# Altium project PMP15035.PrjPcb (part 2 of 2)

## Sheet LM5170ControllerStage1.SchDoc
size 431 x 279 mm; Date: Not shown in title block; ApprovedBy: Not shown in title block; CheckedBy: Not shown in title block; Author: Not shown in title block; CompanyName: Not shown in title block; Engineer: Not shown in title block; Organization: Not shown in title block; Address1: Not shown in title block; Address2: Not shown in title block; Address3: Not shown in title block; Address4: Not shown in title block; DocumentNumber: 4; Revision: Use project parameter SCH_Rev; SheetNumber: 4; SheetTotal: 9; PageSetup: Record=PageOptions¦CenterHorizontal=True¦CenterVertical=True¦PrintScale=1.00¦XCorrection=1.00¦YCorrection=1.00¦PrintKind=0¦BorderSize=5000000¦LeftOffset=0¦BottomOffset=0¦Orientation=2¦PaperLength=1000¦PaperWidth=1000¦Scale=100¦PaperSource=15¦PrintQuality=600¦MediaType=1¦DitherType=10¦PaperKind=Letter¦PrintScaleMode=1
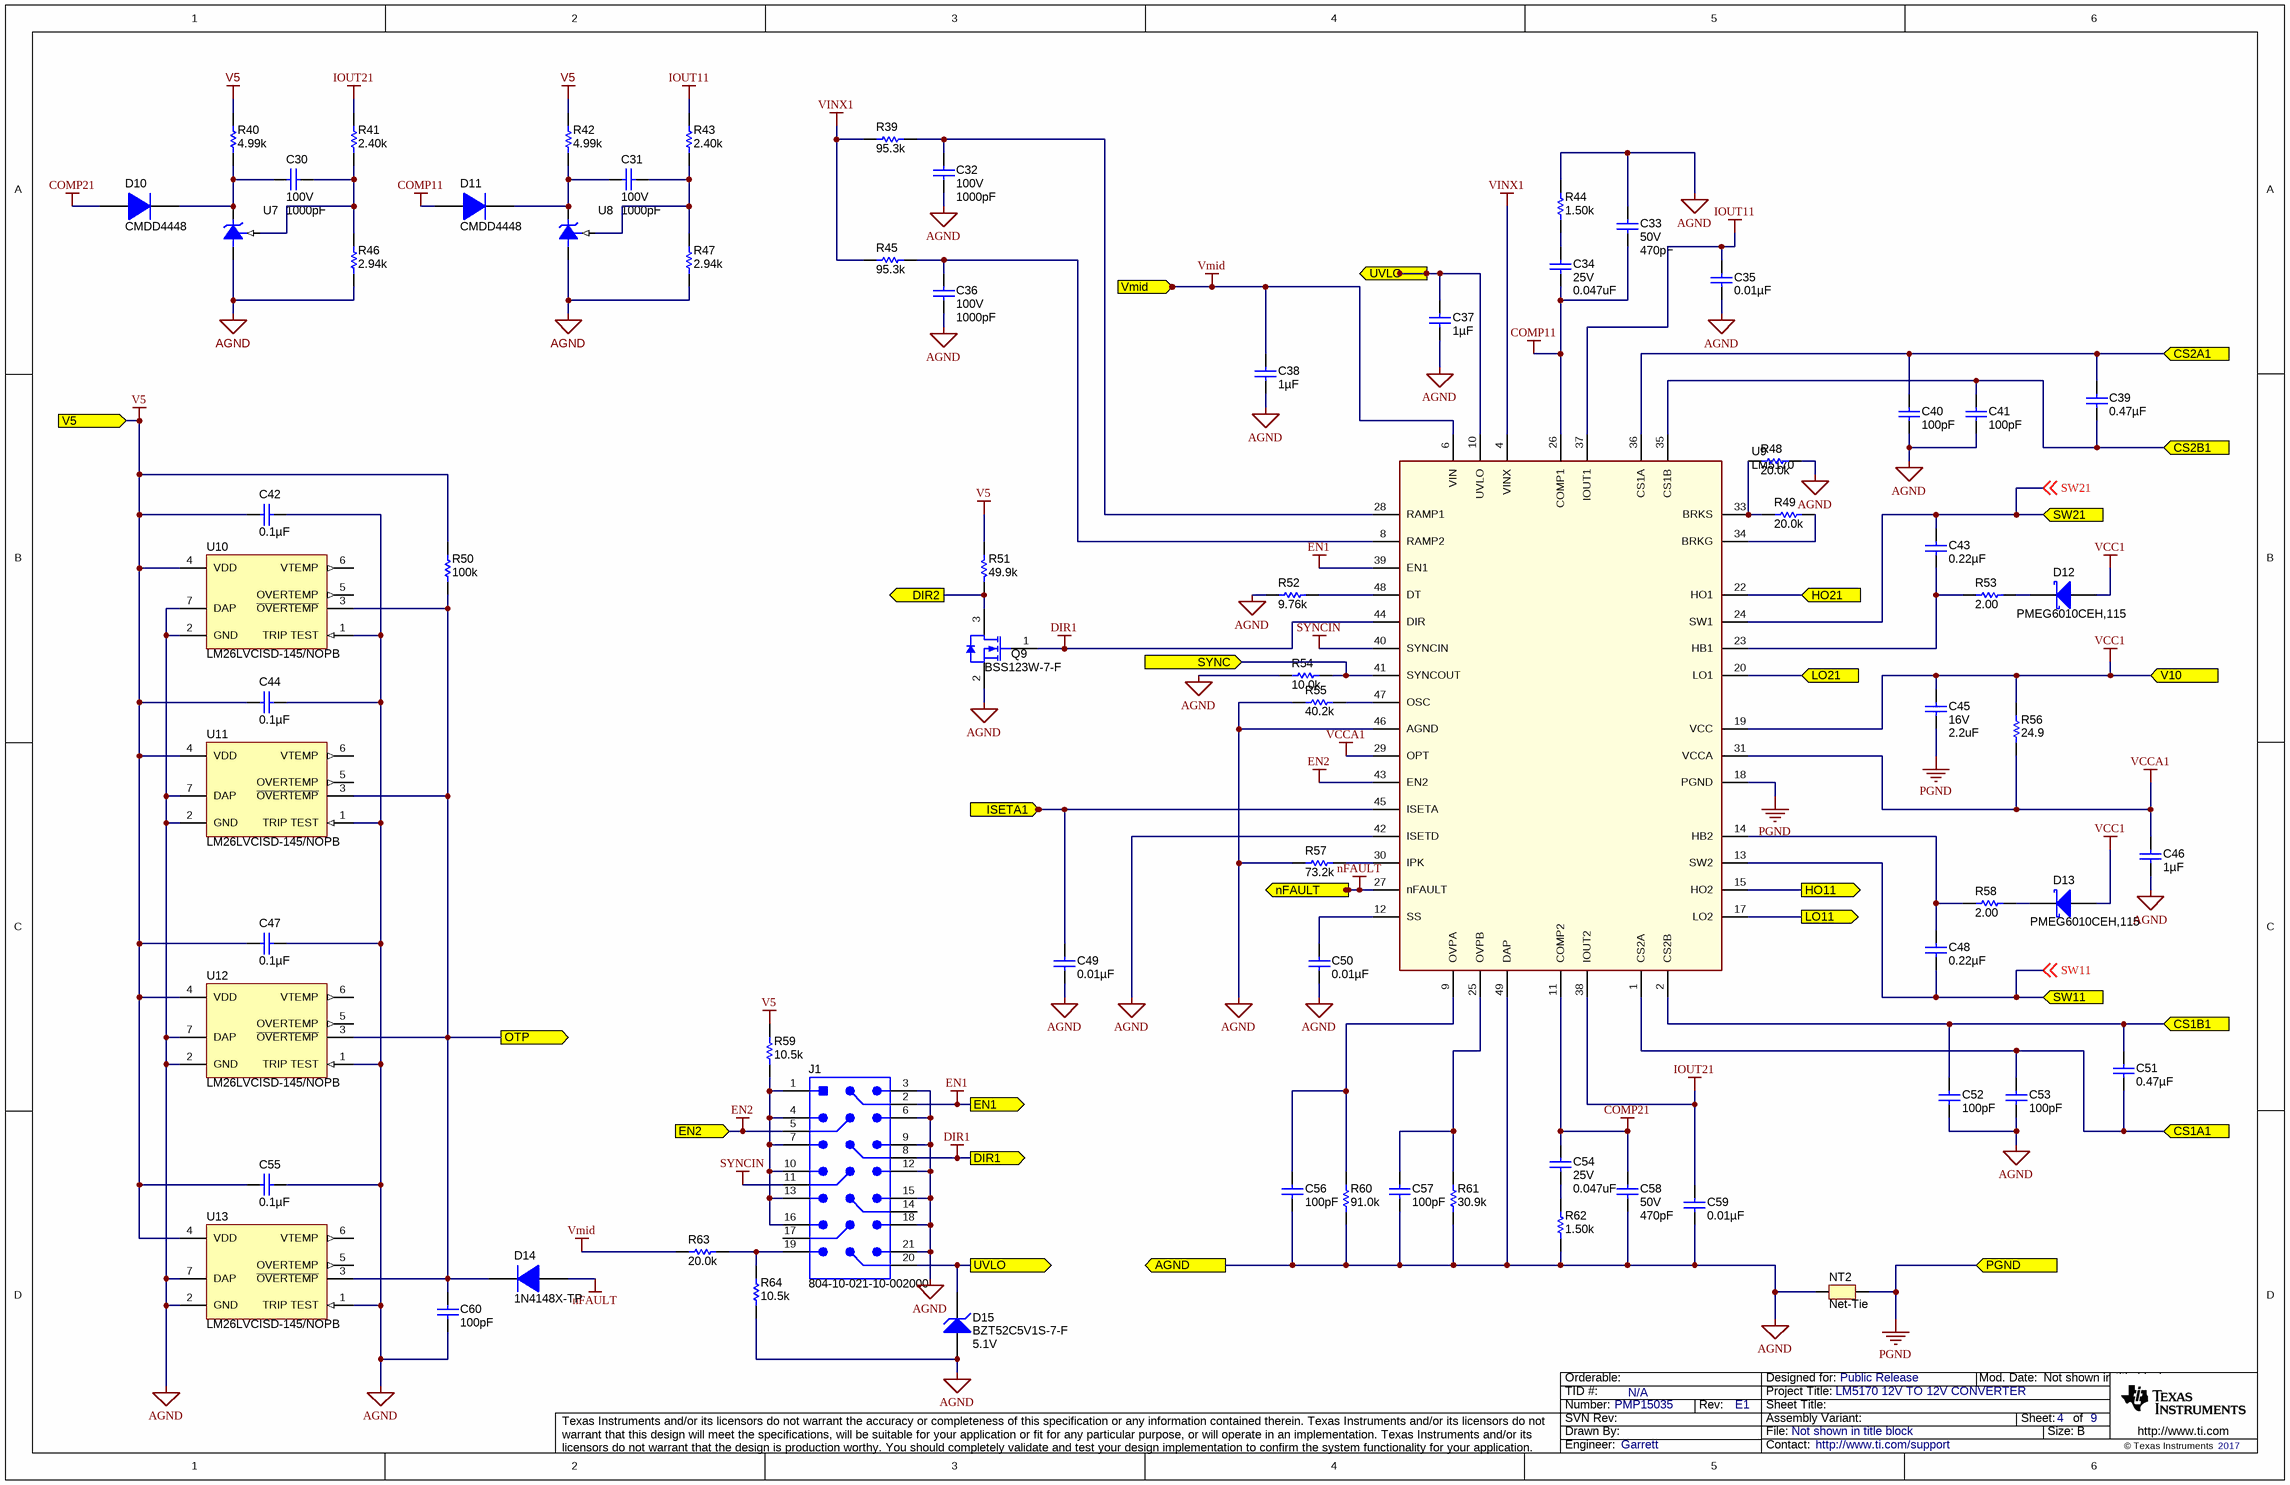
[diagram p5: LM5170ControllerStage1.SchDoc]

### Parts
C30  VDC_V: 100V  ValueDisplayed: 1000pF  [0603L]  (hidden comment: C1608C0G2A102J080AA)
C31  VDC_V: 100V  ValueDisplayed: 1000pF  [0603L]  (hidden comment: C1608C0G2A102J080AA)
C32  VDC_V: 100V  ValueDisplayed: 1000pF  [0603L]  (hidden comment: C1608C0G2A102J080AA)
C33  VDC_V: 50V  ValueDisplayed: 470pF  [0603]  (hidden comment: 885012206081)
C34  VDC_V: 25V  ValueDisplayed: 0.047uF  [0603]  (hidden comment: GRM188R71E473KA01D)
C35  ValueDisplayed: 0.01µF  [0603L]  (hidden comment: 06031C103KAT2A)
C36  VDC_V: 100V  ValueDisplayed: 1000pF  [0603L]  (hidden comment: C1608C0G2A102J080AA)
C37  ValueDisplayed: 1µF  [0805_HV]  (hidden comment: C2012X7S2A105K125AB)
C38  ValueDisplayed: 1µF  [0805_HV]  (hidden comment: C2012X7S2A105K125AB)
C39  ValueDisplayed: 0.47µF  [0603L]  (hidden comment: GRM188R71C474KA88D)
C40  ValueDisplayed: 100pF  [0603L]  (hidden comment: C0603C101J5GACTU)
C41  ValueDisplayed: 100pF  [0603L]  (hidden comment: C0603C101J5GACTU)
C42  ValueDisplayed: 0.1µF  [0603L]  (hidden comment: GRM188R72A104KA35D)
C43  ValueDisplayed: 0.22µF  [0603L]  (hidden comment: C1608X7R1H224K080AB)
C44  ValueDisplayed: 0.1µF  [0603L]  (hidden comment: GRM188R72A104KA35D)
C45  VDC_V: 16V  ValueDisplayed: 2.2uF  [0805_HV]  (hidden comment: C2012X7R1C225K125AB)
C46  ValueDisplayed: 1µF  [0603L]  (hidden comment: GRM188R71E105KA12D)
C47  ValueDisplayed: 0.1µF  [0603L]  (hidden comment: GRM188R72A104KA35D)
C48  ValueDisplayed: 0.22µF  [0603L]  (hidden comment: C1608X7R1H224K080AB)
C49  ValueDisplayed: 0.01µF  [0603L]  (hidden comment: 06031C103KAT2A)
C50  ValueDisplayed: 0.01µF  [0603L]  (hidden comment: 06031C103KAT2A)
C51  ValueDisplayed: 0.47µF  [0603L]  (hidden comment: GRM188R71C474KA88D)
C52  ValueDisplayed: 100pF  [0603L]  (hidden comment: C0603C101J5GACTU)
C53  ValueDisplayed: 100pF  [0603L]  (hidden comment: C0603C101J5GACTU)
C54  VDC_V: 25V  ValueDisplayed: 0.047uF  [0603]  (hidden comment: GRM188R71E473KA01D)
C55  ValueDisplayed: 0.1µF  [0603L]  (hidden comment: GRM188R72A104KA35D)
C56  ValueDisplayed: 100pF  [0603L]  (hidden comment: C0603C101J5GACTU)
C57  ValueDisplayed: 100pF  [0603L]  (hidden comment: C0603C101J5GACTU)
C58  VDC_V: 50V  ValueDisplayed: 470pF  [0603]  (hidden comment: 885012206081)
C59  ValueDisplayed: 0.01µF  [0603L]  (hidden comment: 06031C103KAT2A)
C60  ValueDisplayed: 100pF  [0603L]  (hidden comment: C0603C101J5GACTU)
D10  CMDD4448  [sod-323]
D11  CMDD4448  [sod-323]
D12  PMEG6010CEH,115  [SOD-123F]
D13  PMEG6010CEH,115  [SOD-123F]
D14  1N4148X-TP  [SOD-523]
D15  BZT52C5V1S-7-F  value 5.1V  [SOD-323]
J1  804-10-021-10-002000  [Mill-Max_804-10-021-10-002000]
NT2  Net-Tie  [Net-Tie_10mil]  (net tie, no BOM)
Q9  BSS123W-7-F  [SOT-323]
R39  ValueDisplayed: 95.3k  [0603L]  (hidden comment: CRCW060395K3FKEA)
R40  ValueDisplayed: 4.99k  [0603L]  (hidden comment: CRCW06034K99FKEA)
R41  ValueDisplayed: 2.40k  [0603]  (hidden comment: RC0603FR-072K4L)
R42  ValueDisplayed: 4.99k  [0603L]  (hidden comment: CRCW06034K99FKEA)
R43  ValueDisplayed: 2.40k  [0603]  (hidden comment: RC0603FR-072K4L)
R44  ValueDisplayed: 1.50k  [0603]  (hidden comment: RC0603FR-071K5L)
R45  ValueDisplayed: 95.3k  [0603L]  (hidden comment: CRCW060395K3FKEA)
R46  ValueDisplayed: 2.94k  [0603]  (hidden comment: RC0603FR-072K94L)
R47  ValueDisplayed: 2.94k  [0603]  (hidden comment: RC0603FR-072K94L)
R48  ValueDisplayed: 20.0k  [0603]  (hidden comment: RC0603FR-0720KL)
R49  ValueDisplayed: 20.0k  [0603]  (hidden comment: RC0603FR-0720KL)
R50  ValueDisplayed: 100k  [0402]  (hidden comment: CRCW0402100KFKED)
R51  ValueDisplayed: 49.9k  [0603L]  (hidden comment: CRCW060349K9FKEA)
R52  ValueDisplayed: 9.76k  [0603]  (hidden comment: RC0603FR-079K76L)
R53  ValueDisplayed: 2.00  [0805_HV]  (hidden comment: RC0805FR-072RL)
R54  ValueDisplayed: 10.0k  [0603L]  (hidden comment: CRCW060310K0FKEA)
R55  ValueDisplayed: 40.2k  [0603]  (hidden comment: RC0603FR-0740K2L)
R56  ValueDisplayed: 24.9  [0805L]  (hidden comment: CRCW080524R9FKEA)
R57  ValueDisplayed: 73.2k  [0603]  (hidden comment: RC0603FR-0773K2L)
R58  ValueDisplayed: 2.00  [0805_HV]  (hidden comment: RC0805FR-072RL)
R59  ValueDisplayed: 10.5k  [0603L]  (hidden comment: RC0603FR-0710K5L)
R60  ValueDisplayed: 91.0k  [0603]  (hidden comment: RC0603FR-0791KL)
R61  ValueDisplayed: 30.9k  [0603]  (hidden comment: RC0603FR-0730K9L)
R62  ValueDisplayed: 1.50k  [0603]  (hidden comment: RC0603FR-071K5L)
R63  ValueDisplayed: 20.0k  [0603]  (hidden comment: RC0603FR-0720KL)
R64  ValueDisplayed: 10.5k  [0603L]  (hidden comment: RC0603FR-0710K5L)
U7  LMV431BIMF/NOPB  [DBZ0003A_N]  (value not drawn)
U8  LMV431BIMF/NOPB  [DBZ0003A_N]  (value not drawn)
U9  LM5170  [PHP0048D_L]
U10  LM26LVCISD-145/NOPB  [SDB06A]
U11  LM26LVCISD-145/NOPB  [SDB06A]
U12  LM26LVCISD-145/NOPB  [SDB06A]
U13  LM26LVCISD-145/NOPB  [SDB06A]

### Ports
AGND, CS1A1, CS1B1, CS2A1, CS2B1, DIR1, DIR2, EN1, EN2, HO11, HO21, ISETA1, LO11, LO21, nFAULT, OTP, PGND, SW11, SW21, SYNC, UVLO, V5, V10, Vmid

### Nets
AGND: C32.2 C33.1 C35.2 C36.2 C37.2 C38.2 C40.2 C41.2 C42.2 C44.2 C46.2 C47.2 C49.2 C50.2 C52.2 C53.2 C55.2 C56.2 C57.2 C58.2 C59.2 C60.2 D15.2(A) J1.3 J1.6 J1.9 J1.12 J1.15 J1.18 J1.21 NT2.1 Q9.2(S) R44.2 R46.1 R47.1 R48.2 R52.2 R54.1 R55.1 R57.1 R60.1 R61.1 R62.1 R64.1 U7.3(A) U8.3(A) U9.42(ISETD) U9.46(AGND) U9.49(DAP) U10.1(TRIP_TEST) U10.2(GND) U10.7(DAP) U11.1(TRIP_TEST) U11.2(GND) U11.7(DAP) U12.1(TRIP_TEST) U12.2(GND) U12.7(DAP) U13.1(TRIP_TEST) U13.2(GND) U13.7(DAP) ; port AGND
COMP11: C33.2 C34.2 D11.2(A) U9.26(COMP1)
COMP21: C54.1 C58.1 D10.2(A) U9.11(COMP2)
DIR1: J1.8 Q9.1(G) U9.44(DIR) ; port DIR1
EN1: J1.2 U9.39(EN1) ; port EN1
EN2: J1.5 U9.43(EN2) ; port EN2
IOUT11: C35.1 R43.2 U9.37(IOUT1)
IOUT21: C59.1 R41.2 U9.38(IOUT2)
nFAULT: D14.2(A) U9.27(nFAULT) ; port nFAULT
PGND: C45.2 NT2.2 U9.18(PGND) ; port PGND
SYNCIN: J1.11 U9.40(SYNCIN)
V5: C42.1 C44.1 C47.1 C55.1 R40.1 R42.1 R50.2 R51.2 R59.2 U10.4(VDD) U11.4(VDD) U12.4(VDD) U13.4(VDD) ; port V5
VCC1: C45.1 D12.2(A) D13.2(A) R56.2 U9.19(VCC) ; port V10
VCCA1: C46.1 R56.1 U9.29(OPT) U9.31(VCCA)
VINX1: R39.1 R45.1 U9.4(VINX)
Vmid: C38.1 R63.1 U9.6(VIN) ; port Vmid
CS1A1: C51.2 C53.1 U9.1(CS2A) ; port CS1A1
CS1B1: C51.1 C52.1 U9.2(CS2B) ; port CS1B1
CS2A1: C39.1 C40.1 U9.36(CS1A) ; port CS2A1
CS2B1: C39.2 C41.1 U9.35(CS1B) ; port CS2B1
DIR2: Q9.3(D) R51.1 ; port DIR2
HO11: U9.15(HO2) ; port HO11
HO21: U9.22(HO1) ; port HO21
ISETA1: C49.1 U9.45(ISETA) ; port ISETA1
LO11: U9.17(LO2) ; port LO11
LO21: U9.20(LO1) ; port LO21
OTP: C60.1 D14.1(K) R50.1 U10.3(~{OVERTEMP}) U11.3(~{OVERTEMP}) U12.3(~{OVERTEMP}) U13.3(~{OVERTEMP}) ; port OTP
SW11: C48.2 U9.13(SW2) ; off-sheet SW11, port SW11
SW21: C43.1 U9.24(SW1) ; off-sheet SW21, port SW21
SYNC: R54.2 U9.41(SYNCOUT) ; port SYNC
UVLO: C37.1 D15.1(K) J1.20 U9.10(UVLO) ; port UVLO
NetC30_1: C30.1 R41.1 R46.2 U7.1(REF)
NetC30_2: C30.2 D10.1(K) R40.2 U7.2(K)
NetC31_1: C31.1 R43.1 R47.2 U8.1(REF)
NetC31_2: C31.2 D11.1(K) R42.2 U8.2(K)
NetC32_1: C32.1 R39.2 U9.28(RAMP1)
NetC34_1: C34.1 R44.1
NetC36_1: C36.1 R45.2 U9.8(RAMP2)
NetC43_2: C43.2 R53.1 U9.23(HB1)
NetC48_1: C48.1 R58.1 U9.14(HB2)
NetC50_1: C50.1 U9.12(SS)
NetC54_2: C54.2 R62.2
NetC56_1: C56.1 R60.2 U9.9(OVPA)
NetC57_1: C57.1 R61.2 U9.25(OVPB)
NetD12_1: D12.1(K) R53.2
NetD13_1: D13.1(K) R58.2
NetJ1_1: J1.1 J1.4 J1.7 J1.10 J1.13 J1.16 R59.1
NetJ1_19: J1.19 R63.2 R64.2
NetR48_1: R48.1 R49.1 U9.33(BRKS)
NetR49_2: R49.2 U9.34(BRKG)
NetR52_1: R52.1 U9.48(DT)
NetR55_2: R55.2 U9.47(OSC)
NetR57_2: R57.2 U9.30(IPK)

Not connected (* = marked no-connect by the designer): J1 14 17; U10 5(OVERTEMP) 6(VTEMP); U11 5(OVERTEMP) 6(VTEMP); U12 5(OVERTEMP) 6(VTEMP); U13 5(OVERTEMP) 6(VTEMP)

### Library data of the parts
C30-C32 C36 = CMP-0006993-4: CAP, CERM, 1000 pF, 100 V, +/- 5%, C0G/NP0, 0603; Manufacturer: TDK; TaMin_C: -55°C; ESR_ohm: 0.0589; Polarized: N; SizeAreaWB_mm2: 4.68; Value1: 0.0589 ohm; U/M: EA; Value: 1000pF; TaMax_C: 125°C; SizeZ_mm: 1; SizeX_mm: 1.6; SizeY_mm: 0.8; Cap_Case: 0603; SizeArea_mm2: 1.28; CompType: Capacitor; Cap_F: 1nF; AEC Category: Q200
C33 C58 = CMP-0006834-5: CAP, CERM, 470 pF, 50 V, +/- 10%, X7R, 0603; Manufacturer: Wurth Elektronik; TaMin_C: -55°C; Polarized: N; SizeAreaWB_mm2: 4.68; Value1: Unknown; U/M: EA; Value: 470pF; TaMax_C: 125°C; SizeZ_mm: 1; SizeX_mm: 1.6; SizeY_mm: 0.8; SizeArea_mm2: 1.28; CompType: Capacitor; AEC Category: Q200
C34 C54 = CMP-0007423-4: CAP, CERM, 0.047 uF, 25 V, +/- 10%, X7R, 0603; Manufacturer: MuRata; TaMin_C: -55°C; Polarized: N; SizeAreaWB_mm2: 4.68; Value1: Unknown; U/M: EA; TaMax_C: 125°C; SizeZ_mm: 1; SizeX_mm: 1.6; SizeY_mm: 0.8; SizeArea_mm2: 1.28; CompType: Capacitor; Cap_F: 47nF; AEC Category: Q200
C35 C50 C59 = 06031C103KAT2A: CAP, CERM, 0.01 µF, 100 V, +/- 10%, X7R, 0603; Manufacturer: AVX; Polarized: N; CompType: Capacitor; Value: 0.01uF; U/M: EA; Cap_F: 0.00000001; Tolerance_%: 10; ESR_ohm: 0.098; Value1: 0.098 ohm; VDC_V: 100; Value2: 100V; TaMin_C: -55; TaMax_C: 125; Cap_Case: 0603
C37 C38 = C2012X7S2A105K125AB: CAP, CERM, 1 µF, 100 V, +/- 10%, X7S, 0805; Manufacturer: TDK; Polarized: N; CompType: Capacitor; Value: 1uF; U/M: EA; Cap_F: 0.000001; Tolerance_%: 10; Value1: Unknown; VDC_V: 100; Value2: 100V; TaMin_C: -55; TaMax_C: 125; Cap_Case: 0805; AEC Category: Q200
C39 C51 = GRM188R71C474KA88D: CAP, CERM, 0.47 µF, 16 V, +/- 10%, X7R, 0603; Manufacturer: MuRata; Polarized: N; CompType: Capacitor; Value: 0.47uF; U/M: EA; Cap_F: 0.00000047; Tolerance_%: 10; Value1: Unknown; VDC_V: 16; Value2: 16V; TaMin_C: -55; TaMax_C: 125; Cap_Case: 0603; AEC Category: Q200
C40 C41 C52 C53 C56 C57 C60 = C0603C101J5GACTU: CAP, CERM, 100 pF, 50 V, +/- 5%, C0G/NP0, 0603; Manufacturer: Kemet; Polarized: N; CompType: Capacitor; Value: 100pF; U/M: EA; Cap_F: 0.0000000001; Tolerance_%: 5; Value1: Unknown; VDC_V: 50; Value2: 50V; TaMin_C: -55; TaMax_C: 125; Cap_Case: 0603; AEC Category: Q200
C42 C44 C47 C55 = GRM188R72A104KA35D: CAP, CERM, 0.1 µF, 100 V, +/- 10%, X7R, 0603; Manufacturer: MuRata; Polarized: N; CompType: Capacitor; Value: 0.1uF; U/M: EA; Cap_F: 0.0000001; Tolerance_%: 10; Value1: Unknown; VDC_V: 100; Value2: 100V; TaMin_C: -55; TaMax_C: 125; Cap_Case: 0603; AEC Category: Q200
C43 C48 = C1608X7R1H224K080AB: CAP, CERM, 0.22 µF, 50 V, +/- 10%, X7R, 0603; Manufacturer: TDK; Polarized: N; CompType: Capacitor; Value: 0.22uF; U/M: EA; Cap_F: 0.00000022; Tolerance_%: 10; Value1: Unknown; VDC_V: 50; Value2: 50V; TaMin_C: -55; TaMax_C: 125; Cap_Case: 0603
C45 = CMP-0007867-2: CAP, CERM, 2.2 uF, 16 V, +/- 10%, X7R, 0805; Manufacturer: TDK; TaMin_C: -55°C; ESR_ohm: 4.9m; Polarized: N; SizeAreaWB_mm2: 6.75; Value1: 0.0049 ohm; U/M: EA; Value: 2.2uF; TaMax_C: 125°C; SizeZ_mm: 1.45; SizeX_mm: 2; SizeY_mm: 1.25; Cap_Case: 0805; SizeArea_mm2: 2.5; CompType: Capacitor; Cap_F: 2.2µF; AEC Category: Q200
C46 = GRM188R71E105KA12D: CAP, CERM, 1 µF, 25 V, +/- 10%, X7R, 0603; Manufacturer: MuRata; Polarized: N; CompType: Capacitor; Value: 1uF; U/M: EA; Cap_F: 0.000001; Tolerance_%: 10; Value1: Unknown; VDC_V: 25; Value2: 25V; TaMin_C: -55; TaMax_C: 125; Cap_Case: 0603
C49 = 06031C103KAT2A: CAP, CERM, 0.01 µF, 100 V, +/- 10%, X7R, 0603; Manufacturer: AVX; Polarized: N; CompType: Capacitor; Value: 0.01uF; U/M: EA; Cap_F: 0.00000001; Tolerance_%: 10; ESR_ohm: 0.098; Value1: 0.098 ohm; VDC_V: 100; Value2: 100V; TaMin_C: -55; TaMax_C: 125; Cap_Case: 0603; AEC Category: Q200
D10 D11 = CMDD4448: Diode, Ultrafast, 75 V, 0.25 A, SOD-323; Manufacturer: Central Semiconductor; U/M: EA; Vf_V: 1.2; Value: 75V; Value1: 0.25A; Value2: 1.2V; Io_A: 0.25; Vr_V: 75; TJmax_C: 175
D12 D13 = PMEG6010CEH,115: Diode, Schottky, 60 V, 1 A, SOD-123F; Manufacturer: NXP Semiconductor; U/M: EA; Vf_V: 0.57; Value: 60V; Value1: 1A; Value2: 0.57V; Io_A: 1; Vr_V: 60; TJmax_C: 150
D14 = 1N4148X-TP: Diode, Switching, 75 V, 0.3 A, SOD-523; Manufacturer: Micro Commercial Components; U/M: EA; Vf_V: 1.25; Value: 75V; Value1: 0.3A; Value2: 1.25V; Io_A: 0.3; Vr_V: 75; TJmax_C: 150; RJC_CperW: 625
D15 = CMP-0005865-1: Diode, Zener, 5.1 V, 200 mW, SOD-323; Manufacturer: Diodes Inc.; Power_W: 200mW; SizeAreaWB_mm2: 8.695; Value1: 0.2W; RJA_CperW: 625; U/M: EA; SizeZ_mm: 1; SizeX_mm: 2.7; SizeY_mm: 1.35; SizeArea_mm2: 3.645; AEC Category: Q101
J1 = CMP-0055099-1: Header, 2.54 mm, 7x3, Gold, Vertical, TH; Manufacturer: Mill-Max; CNHeader: TRUE; Shrouded: N; Gender: Male; Row_Count: 3; RowSpacing_mm: 2.54; CT: FALSE
NT2 = Net-Tie: Single point connection between nets.; SymbolCreator: codlsc
Q9 = CMP-0000948-2: MOSFET, N-CH, 100 V, 0.17 A, SOT-323; Alternate Manufacturer: None; Manufacturer: Diodes Inc.; SizeZ_mm: 1.1; ChType: N; Value1: 1; VdsMax_V: 100V; SizeX_mm: 2.2; Vgs_V: 20V; Value: 100V; Rdson45_ohm: 10; SizeArea_mm2: 4.84; AEC Category: Q101; IdsMax_A: 1.7dA; SizeAreaWB_mm2: 10.24; U/M: EA
R39 R45 = CRCW060395K3FKEA: RES, 95.3 k, 1%, 0.1 W, 0603; Manufacturer: Vishay-Dale; CompType: Resistor; Value: 95.3k; Res_ohm: 95300; Value_Code: 95k3; Tolerance_%: 1; Power_W: 0.1; Value2: 0.1W; VDC_V: 75; TempCo: 100 ppm/C; EIA_Code: E96; U/M: EA
R40 R42 = CRCW06034K99FKEA: RES, 4.99 k, 1%, 0.1 W, 0603; Manufacturer: Vishay-Dale; CompType: Resistor; Value: 4.99k; Res_ohm: 4990; Value_Code: 4k99; Tolerance_%: 1; Power_W: 0.1; Value2: 0.1W; VDC_V: 75; TempCo: 100 ppm/C; EIA_Code: E96; U/M: EA
R41 R43 = CMP-0022991-3: RES, 2.40 k, 1%, 0.1 W, 0603; Manufacturer: Yageo America; Power_W: 100mW; TempCo: 200 ppm/C; Value_Code: 2k40; U/M: EA; Value: 2.40k; Res_ohm: 2.4k; SizeX_mm: 1.6; SizeY_mm: 0.8; SizeZ_mm: 1; Value2: 0.1W; SizeArea_mm2: 1.28; CompType: Resistor; VDC_V: 150V; AEC Category: Q200
R44 R62 = CMP-0022883-3: RES, 1.50 k, 1%, 0.1 W, 0603; Manufacturer: Yageo America; Power_W: 100mW; TempCo: 200 ppm/C; Value_Code: 1k50; U/M: EA; Value: 1.50k; EIA_Code: E96; Res_ohm: 1.5k; SizeX_mm: 1.6; SizeY_mm: 0.8; SizeZ_mm: 1; Value2: 0.1W; SizeArea_mm2: 1.28; CompType: Resistor; VDC_V: 150V; AEC Category: Q200
R46 R47 = CMP-0022999-3: RES, 2.94 k, 1%, 0.1 W, 0603; Manufacturer: Yageo America; Power_W: 100mW; TempCo: 200 ppm/C; Value_Code: 2k94; U/M: EA; Value: 2.94k; EIA_Code: E96; SizeX_mm: 1.6; SizeY_mm: 0.8; SizeZ_mm: 1; Value2: 0.1W; SizeArea_mm2: 1.28; CompType: Resistor; VDC_V: 150V; AEC Category: Q200
R48 R49 R63 = CMP-0022906-3: RES, 20.0 k, 1%, 0.1 W, 0603; Manufacturer: Yageo America; Power_W: 100mW; TempCo: 200 ppm/C; Value_Code: 20k0; U/M: EA; Value: 20.0k; EIA_Code: E96; Res_ohm: 20k; SizeX_mm: 1.6; SizeY_mm: 0.8; SizeZ_mm: 1; Value2: 0.1W; SizeArea_mm2: 1.28; CompType: Resistor; VDC_V: 150V; AEC Category: Q200
R50 = CRCW0402100KFKED: RES, 100 k, 1%, 0.063 W, 0402; Manufacturer: Vishay-Dale; CompType: Resistor; Value: 100k; Res_ohm: 100000; Tolerance_%: 1; Power_W: 0.063; Value2: 0.063W; VDC_V: 50; TempCo: 100 ppm/C; EIA_Code: E96; U/M: EA
R51 = CRCW060349K9FKEA: RES, 49.9 k, 1%, 0.1 W, 0603; Manufacturer: Vishay-Dale; CompType: Resistor; Value: 49.9k; Res_ohm: 49900; Value_Code: 49k9; Tolerance_%: 1; Power_W: 0.1; Value2: 0.1W; VDC_V: 75; TempCo: 100 ppm/C; EIA_Code: E96; U/M: EA
R52 = CMP-0023336-3: RES, 9.76 k, 1%, 0.1 W, 0603; Manufacturer: Yageo America; Power_W: 100mW; TempCo: 200 ppm/C; Value_Code: 9k76; U/M: EA; Value: 9.76k; EIA_Code: E96; SizeX_mm: 1.6; SizeY_mm: 0.8; SizeZ_mm: 1; Value2: 0.1W; SizeArea_mm2: 1.28; CompType: Resistor; VDC_V: 150V; AEC Category: Q200
R53 R58 = CMP-0021913-2: RES, 2.00, 1%, 0.125 W, 0805; Manufacturer: Yageo America; Power_W: 125mW; TempCo: 200 ppm/C; Value_Code: 2R00; U/M: EA; Value: 2.00; EIA_Code: E96; Res_ohm: 2; SizeY_mm: 1.25; SizeZ_mm: 1.45; Value2: 0.125W; SizeArea_mm2: 2.5; CompType: Resistor; VDC_V: 150V; AEC Category: Q200
R54 = CRCW060310K0FKEA: RES, 10.0 k, 1%, 0.1 W, 0603; Manufacturer: Vishay-Dale; CompType: Resistor; Value: 10.0k; Res_ohm: 10000; Value_Code: 10k0; Tolerance_%: 1; Power_W: 0.1; Value2: 0.1W; VDC_V: 75; TempCo: 100 ppm/C; EIA_Code: E96; U/M: EA
R55 = CMP-0023098-3: RES, 40.2 k, 1%, 0.1 W, 0603; Manufacturer: Yageo America; Power_W: 100mW; TempCo: 200 ppm/C; Value_Code: 40k2; U/M: EA; Value: 40.2k; EIA_Code: E96; SizeX_mm: 1.6; SizeY_mm: 0.8; SizeZ_mm: 1; Value2: 0.1W; SizeArea_mm2: 1.28; CompType: Resistor; VDC_V: 150V; AEC Category: Q200
R56 = CRCW080524R9FKEA: RES, 24.9, 1%, 0.125 W, 0805; Manufacturer: Vishay-Dale; CompType: Resistor; Value: 24.9; Value_Code: 24R9; Tolerance_%: 1; Power_W: 0.125; Value2: 0.125W; VDC_V: 150; TempCo: 100 ppm/C; EIA_Code: E96; U/M: EA
R57 = CMP-0023263-3: RES, 73.2 k, 1%, 0.1 W, 0603; Manufacturer: Yageo America; Power_W: 100mW; TempCo: 200 ppm/C; Value_Code: 73k2; U/M: EA; Value: 73.2k; EIA_Code: E96; SizeX_mm: 1.6; SizeY_mm: 0.8; SizeZ_mm: 1; Value2: 0.1W; SizeArea_mm2: 1.28; CompType: Resistor; VDC_V: 150V; AEC Category: Q200
R59 = CMP-0022744-3: RES, 10.5 k, 1%, 0.1 W, 0603; Manufacturer: Yageo America; Power_W: 100mW; TempCo: 200 ppm/C; Value_Code: 10k5; U/M: EA; Value: 10.5k; EIA_Code: E96; SizeX_mm: 1.6; SizeY_mm: 0.8; SizeZ_mm: 1; Value2: 0.1W; SizeArea_mm2: 1.28; CompType: Resistor; VDC_V: 150V; AEC Category: Q200
R60 = CMP-0023318-3: RES, 91.0 k, 1%, 0.1 W, 0603; Manufacturer: Yageo America; Power_W: 100mW; TempCo: 200 ppm/C; Value_Code: 91k0; U/M: EA; Value: 91.0k; Res_ohm: 91k; SizeX_mm: 1.6; SizeY_mm: 0.8; SizeZ_mm: 1; Value2: 0.1W; SizeArea_mm2: 1.28; CompType: Resistor; VDC_V: 150V; AEC Category: Q200
R61 = CMP-0023019-3: RES, 30.9 k, 1%, 0.1 W, 0603; Manufacturer: Yageo America; Power_W: 100mW; TempCo: 200 ppm/C; Value_Code: 30k9; U/M: EA; Value: 30.9k; EIA_Code: E96; SizeX_mm: 1.6; SizeY_mm: 0.8; SizeZ_mm: 1; Value2: 0.1W; SizeArea_mm2: 1.28; CompType: Resistor; VDC_V: 150V; AEC Category: Q200
R64 = CMP-0022744-3: RES, 10.5 k, 1%, 0.1 W, 0603; Manufacturer: Yageo America; Power_W: 100mW; TempCo: 200 ppm/C; Value_Code: 10k5; U/M: EA; Value: 10.5k; EIA_Code: E96; SizeX_mm: 1.6; SizeY_mm: 0.8; SizeZ_mm: 1; Value2: 0.1W; SizeArea_mm2: 1.28; VDC_V: 150V; AEC Category: Q200
U7 U8 = CMP-0071728-1: Low-Voltage (1.24V) Adjustable Precision Shunt Regulators, 3-pin SOT-23, Pb-Free; Manufacturer: Texas Instruments; PowerWise: N; PackageTopMarking: RLB*XTT; CompType: MiscPower
U9 = LM5170_PreIC: IC, Controller, Bi-Directional; Manufacturer: Texas Instruments; SymbolCreator: a0413446; U/M: EA, IN, or GM
U10-U13 = LM26LVCISD-145/NOPB: 1.6V Factory Preset Temperature Switch and Temperature Sensor, 6-pin LLP, Pb-Free; Manufacturer: Texas Instruments; PackageTopMarking: XTT*145; PowerWise: Y; CompType: Temp Sensor IC

## Sheet LM5170ControllerStage2.SchDoc
size 431 x 279 mm; Date: Not shown in title block; ApprovedBy: Not shown in title block; CheckedBy: Not shown in title block; Author: Not shown in title block; CompanyName: Not shown in title block; Engineer: Not shown in title block; Organization: Not shown in title block; Address1: Not shown in title block; Address2: Not shown in title block; Address3: Not shown in title block; Address4: Not shown in title block; DocumentNumber: 5; Revision: Use project parameter SCH_Rev; SheetNumber: 5; SheetTotal: 9; PageSetup: Record=PageOptions¦CenterHorizontal=True¦CenterVertical=True¦PrintScale=1.00¦XCorrection=1.00¦YCorrection=1.00¦PrintKind=0¦BorderSize=5000000¦LeftOffset=0¦BottomOffset=0¦Orientation=2¦PaperLength=1000¦PaperWidth=1000¦Scale=100¦PaperSource=15¦PrintQuality=600¦MediaType=1¦DitherType=10¦PaperKind=Letter¦PrintScaleMode=1
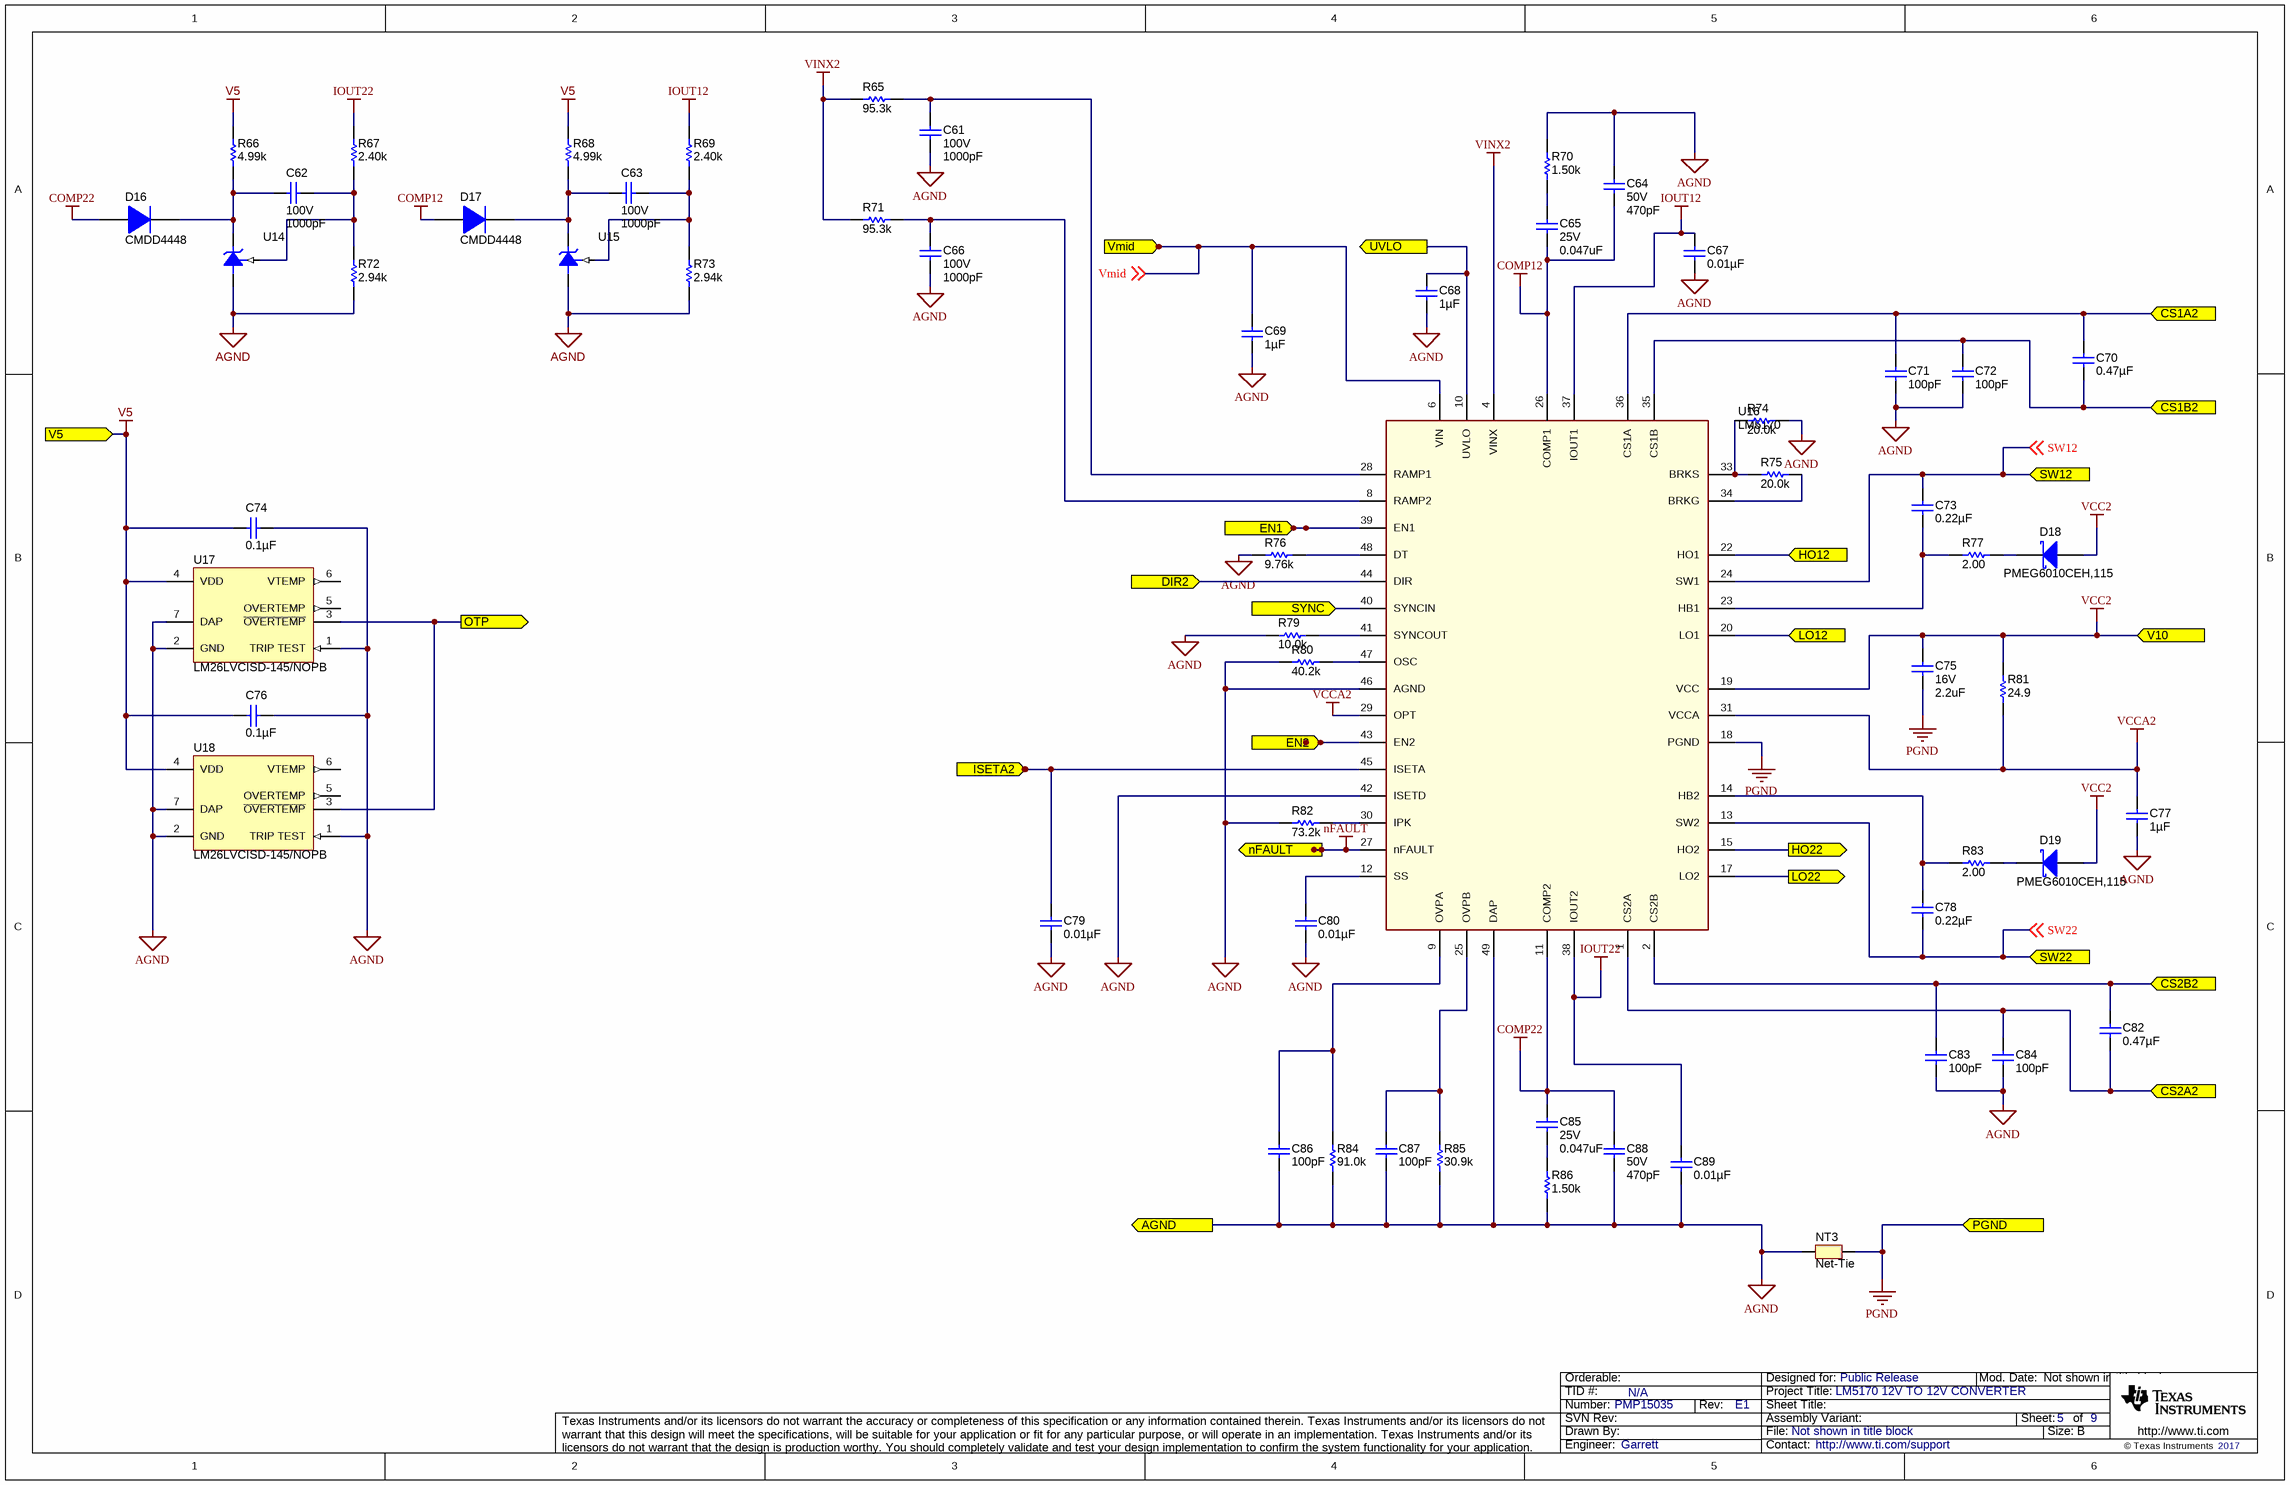
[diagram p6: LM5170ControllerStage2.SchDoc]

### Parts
C61  VDC_V: 100V  ValueDisplayed: 1000pF  [0603L]  (hidden comment: C1608C0G2A102J080AA)
C62  VDC_V: 100V  ValueDisplayed: 1000pF  [0603L]  (hidden comment: C1608C0G2A102J080AA)
C63  VDC_V: 100V  ValueDisplayed: 1000pF  [0603L]  (hidden comment: C1608C0G2A102J080AA)
C64  VDC_V: 50V  ValueDisplayed: 470pF  [0603]  (hidden comment: 885012206081)
C65  VDC_V: 25V  ValueDisplayed: 0.047uF  [0603]  (hidden comment: GRM188R71E473KA01D)
C66  VDC_V: 100V  ValueDisplayed: 1000pF  [0603L]  (hidden comment: C1608C0G2A102J080AA)
C67  ValueDisplayed: 0.01µF  [0603L]  (hidden comment: 06031C103KAT2A)
C68  ValueDisplayed: 1µF  [0805_HV]  (hidden comment: C2012X7S2A105K125AB)
C69  ValueDisplayed: 1µF  [0805_HV]  (hidden comment: C2012X7S2A105K125AB)
C70  ValueDisplayed: 0.47µF  [0603L]  (hidden comment: GRM188R71C474KA88D)
C71  ValueDisplayed: 100pF  [0603L]  (hidden comment: C0603C101J5GACTU)
C72  ValueDisplayed: 100pF  [0603L]  (hidden comment: C0603C101J5GACTU)
C73  ValueDisplayed: 0.22µF  [0603L]  (hidden comment: C1608X7R1H224K080AB)
C74  ValueDisplayed: 0.1µF  [0603L]  (hidden comment: GRM188R72A104KA35D)
C75  VDC_V: 16V  ValueDisplayed: 2.2uF  [0805_HV]  (hidden comment: C2012X7R1C225K125AB)
C76  ValueDisplayed: 0.1µF  [0603L]  (hidden comment: GRM188R72A104KA35D)
C77  ValueDisplayed: 1µF  [0603L]  (hidden comment: GRM188R71E105KA12D)
C78  ValueDisplayed: 0.22µF  [0603L]  (hidden comment: C1608X7R1H224K080AB)
C79  ValueDisplayed: 0.01µF  [0603L]  (hidden comment: 06031C103KAT2A)
C80  ValueDisplayed: 0.01µF  [0603L]  (hidden comment: 06031C103KAT2A)
C82  ValueDisplayed: 0.47µF  [0603L]  (hidden comment: GRM188R71C474KA88D)
C83  ValueDisplayed: 100pF  [0603L]  (hidden comment: C0603C101J5GACTU)
C84  ValueDisplayed: 100pF  [0603L]  (hidden comment: C0603C101J5GACTU)
C85  VDC_V: 25V  ValueDisplayed: 0.047uF  [0603]  (hidden comment: GRM188R71E473KA01D)
C86  ValueDisplayed: 100pF  [0603L]  (hidden comment: C0603C101J5GACTU)
C87  ValueDisplayed: 100pF  [0603L]  (hidden comment: C0603C101J5GACTU)
C88  VDC_V: 50V  ValueDisplayed: 470pF  [0603]  (hidden comment: 885012206081)
C89  ValueDisplayed: 0.01µF  [0603L]  (hidden comment: 06031C103KAT2A)
D16  CMDD4448  [sod-323]
D17  CMDD4448  [sod-323]
D18  PMEG6010CEH,115  [SOD-123F]
D19  PMEG6010CEH,115  [SOD-123F]
NT3  Net-Tie  [Net-Tie_10mil]  (net tie, no BOM)
R65  ValueDisplayed: 95.3k  [0603L]  (hidden comment: CRCW060395K3FKEA)
R66  ValueDisplayed: 4.99k  [0603L]  (hidden comment: CRCW06034K99FKEA)
R67  ValueDisplayed: 2.40k  [0603]  (hidden comment: RC0603FR-072K4L)
R68  ValueDisplayed: 4.99k  [0603L]  (hidden comment: CRCW06034K99FKEA)
R69  ValueDisplayed: 2.40k  [0603]  (hidden comment: RC0603FR-072K4L)
R70  ValueDisplayed: 1.50k  [0603]  (hidden comment: RC0603FR-071K5L)
R71  ValueDisplayed: 95.3k  [0603L]  (hidden comment: CRCW060395K3FKEA)
R72  ValueDisplayed: 2.94k  [0603]  (hidden comment: RC0603FR-072K94L)
R73  ValueDisplayed: 2.94k  [0603]  (hidden comment: RC0603FR-072K94L)
R74  ValueDisplayed: 20.0k  [0603]  (hidden comment: RC0603FR-0720KL)
R75  ValueDisplayed: 20.0k  [0603]  (hidden comment: RC0603FR-0720KL)
R76  ValueDisplayed: 9.76k  [0603]  (hidden comment: RC0603FR-079K76L)
R77  ValueDisplayed: 2.00  [0805_HV]  (hidden comment: RC0805FR-072RL)
R79  ValueDisplayed: 10.0k  [0603L]  (hidden comment: CRCW060310K0FKEA)
R80  ValueDisplayed: 40.2k  [0603]  (hidden comment: RC0603FR-0740K2L)
R81  ValueDisplayed: 24.9  [0805L]  (hidden comment: CRCW080524R9FKEA)
R82  ValueDisplayed: 73.2k  [0603]  (hidden comment: RC0603FR-0773K2L)
R83  ValueDisplayed: 2.00  [0805_HV]  (hidden comment: RC0805FR-072RL)
R84  ValueDisplayed: 91.0k  [0603]  (hidden comment: RC0603FR-0791KL)
R85  ValueDisplayed: 30.9k  [0603]  (hidden comment: RC0603FR-0730K9L)
R86  ValueDisplayed: 1.50k  [0603]  (hidden comment: RC0603FR-071K5L)
U14  LMV431BIMF/NOPB  [DBZ0003A_N]  (value not drawn)
U15  LMV431BIMF/NOPB  [DBZ0003A_N]  (value not drawn)
U16  LM5170  [PHP0048D_L]
U17  LM26LVCISD-145/NOPB  [SDB06A]
U18  LM26LVCISD-145/NOPB  [SDB06A]

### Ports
AGND, CS1A2, CS1B2, CS2A2, CS2B2, DIR2, EN1, EN2, HO12, HO22, ISETA2, LO12, LO22, nFAULT, OTP, PGND, SW12, SW22, SYNC, UVLO, V5, V10, Vmid

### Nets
AGND: C61.2 C64.1 C66.2 C67.2 C68.2 C69.2 C71.2 C72.2 C74.2 C76.2 C77.2 C79.2 C80.2 C83.2 C84.2 C86.2 C87.2 C88.2 C89.2 NT3.1 R70.2 R72.1 R73.1 R74.2 R76.2 R79.1 R80.1 R82.1 R84.1 R85.1 R86.1 U14.3(A) U15.3(A) U16.42(ISETD) U16.46(AGND) U16.49(DAP) U17.1(TRIP_TEST) U17.2(GND) U17.7(DAP) U18.1(TRIP_TEST) U18.2(GND) U18.7(DAP) ; port AGND
COMP12: C64.2 C65.2 D17.2(A) U16.26(COMP1)
COMP22: C85.1 C88.1 D16.2(A) U16.11(COMP2)
EN1: U16.39(EN1) ; port EN1
EN2: U16.43(EN2) ; port EN2
IOUT12: C67.1 R69.2 U16.37(IOUT1)
IOUT22: C89.1 R67.2 U16.38(IOUT2)
nFAULT: U16.27(nFAULT) ; port nFAULT
PGND: C75.2 NT3.2 U16.18(PGND) ; port PGND
V5: C74.1 C76.1 R66.1 R68.1 U17.4(VDD) U18.4(VDD) ; port V5
VCC2: C75.1 D18.2(A) D19.2(A) R81.2 U16.19(VCC) ; port V10  [project net VCC1]
VCCA2: C77.1 R81.1 U16.29(OPT) U16.31(VCCA)
VINX2: R65.1 R71.1 U16.4(VINX)
Vmid: C69.1 U16.6(VIN) ; off-sheet Vmid, port Vmid
CS1A2: C70.1 C71.1 U16.36(CS1A) ; port CS1A2
CS1B2: C70.2 C72.1 U16.35(CS1B) ; port CS1B2
CS2A2: C82.2 C84.1 U16.1(CS2A) ; port CS2A2
CS2B2: C82.1 C83.1 U16.2(CS2B) ; port CS2B2
DIR2: U16.44(DIR) ; port DIR2
HO12: U16.22(HO1) ; port HO12
HO22: U16.15(HO2) ; port HO22
ISETA2: C79.1 U16.45(ISETA) ; port ISETA2
LO12: U16.20(LO1) ; port LO12
LO22: U16.17(LO2) ; port LO22
OTP: U17.3(~{OVERTEMP}) U18.3(~{OVERTEMP}) ; port OTP
SW12: C73.1 U16.24(SW1) ; off-sheet SW12, port SW12
SW22: C78.2 U16.13(SW2) ; off-sheet SW22, port SW22
SYNC: U16.40(SYNCIN) ; port SYNC
UVLO: C68.1 U16.10(UVLO) ; port UVLO
NetC61_1: C61.1 R65.2 U16.28(RAMP1)
NetC62_1: C62.1 R67.1 R72.2 U14.1(REF)
NetC62_2: C62.2 D16.1(K) R66.2 U14.2(K)
NetC63_1: C63.1 R69.1 R73.2 U15.1(REF)
NetC63_2: C63.2 D17.1(K) R68.2 U15.2(K)
NetC65_1: C65.1 R70.1
NetC66_1: C66.1 R71.2 U16.8(RAMP2)
NetC73_2: C73.2 R77.1 U16.23(HB1)
NetC78_1: C78.1 R83.1 U16.14(HB2)
NetC80_1: C80.1 U16.12(SS)
NetC85_2: C85.2 R86.2
NetC86_1: C86.1 R84.2 U16.9(OVPA)
NetC87_1: C87.1 R85.2 U16.25(OVPB)
NetD18_1: D18.1(K) R77.2
NetD19_1: D19.1(K) R83.2
NetR74_1: R74.1 R75.1 U16.33(BRKS)
NetR75_2: R75.2 U16.34(BRKG)
NetR76_1: R76.1 U16.48(DT)
NetR79_2: R79.2 U16.41(SYNCOUT)
NetR80_2: R80.2 U16.47(OSC)
NetR82_2: R82.2 U16.30(IPK)

Not connected (* = marked no-connect by the designer): U17 5(OVERTEMP) 6(VTEMP); U18 5(OVERTEMP) 6(VTEMP)

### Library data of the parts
C61-C63 C66 = CMP-0006993-4: as C30-C32 on sheet LM5170ControllerStage1
C64 C88 = CMP-0006834-5: as C33 on sheet LM5170ControllerStage1
C65 C85 = CMP-0007423-4: as C34 on sheet LM5170ControllerStage1
C67 C80 C89 = 06031C103KAT2A: as C35 on sheet LM5170ControllerStage1
C68 C69 = C2012X7S2A105K125AB: as C37 on sheet LM5170ControllerStage1
C70 C82 = GRM188R71C474KA88D: as C39 on sheet LM5170ControllerStage1
C71 C72 C83 C84 C86 C87 = C0603C101J5GACTU: as C40 on sheet LM5170ControllerStage1
C73 C78 = C1608X7R1H224K080AB: as C43 on sheet LM5170ControllerStage1
C74 C76 = GRM188R72A104KA35D: as C42 on sheet LM5170ControllerStage1
C75 = CMP-0007867-2: as C45 on sheet LM5170ControllerStage1
C77 = GRM188R71E105KA12D: as C46 on sheet LM5170ControllerStage1
C79 = 06031C103KAT2A: as C49 on sheet LM5170ControllerStage1
D16 D17 = CMDD4448: as D10 on sheet LM5170ControllerStage1
D18 D19 = PMEG6010CEH,115: as D12 on sheet LM5170ControllerStage1
NT3 = Net-Tie: as NT2 on sheet LM5170ControllerStage1
R65 R71 = CRCW060395K3FKEA: as R39 on sheet LM5170ControllerStage1
R66 R68 = CRCW06034K99FKEA: as R40 on sheet LM5170ControllerStage1
R67 R69 = CMP-0022991-3: as R41 on sheet LM5170ControllerStage1
R70 R86 = CMP-0022883-3: as R44 on sheet LM5170ControllerStage1
R72 R73 = CMP-0022999-3: as R46 on sheet LM5170ControllerStage1
R74 R75 = CMP-0022906-3: as R48 on sheet LM5170ControllerStage1
R76 = CMP-0023336-3: as R52 on sheet LM5170ControllerStage1
R77 R83 = CMP-0021913-2: as R53 on sheet LM5170ControllerStage1
R79 = CRCW060310K0FKEA: as R54 on sheet LM5170ControllerStage1
R80 = CMP-0023098-3: as R55 on sheet LM5170ControllerStage1
R81 = CRCW080524R9FKEA: as R56 on sheet LM5170ControllerStage1
R82 = CMP-0023263-3: as R57 on sheet LM5170ControllerStage1
R84 = CMP-0023318-3: as R60 on sheet LM5170ControllerStage1
R85 = CMP-0023019-3: as R61 on sheet LM5170ControllerStage1
U14 U15 = CMP-0071728-1: as U7 on sheet LM5170ControllerStage1
U16 = LM5170_PreIC: as U9 on sheet LM5170ControllerStage1
U17 U18 = LM26LVCISD-145/NOPB: as U10 on sheet LM5170ControllerStage1

## Sheet BaisSupply.SchDoc
size 431 x 279 mm; Date: Not shown in title block; ApprovedBy: Not shown in title block; CheckedBy: Not shown in title block; Author: Not shown in title block; CompanyName: Not shown in title block; Engineer: Not shown in title block; Organization: Not shown in title block; Address1: Not shown in title block; Address2: Not shown in title block; Address3: Not shown in title block; Address4: Not shown in title block; DocumentNumber: 8; Revision: Use project parameter SCH_Rev; SheetNumber: 8; SheetTotal: 9; PageSetup: Record=PageOptions¦CenterHorizontal=True¦CenterVertical=True¦PrintScale=1.00¦XCorrection=1.00¦YCorrection=1.00¦PrintKind=0¦BorderSize=5000000¦LeftOffset=0¦BottomOffset=0¦Orientation=2¦PaperLength=1000¦PaperWidth=1000¦Scale=100¦PaperSource=15¦PrintQuality=600¦MediaType=1¦DitherType=10¦PaperKind=Letter¦PrintScaleMode=1
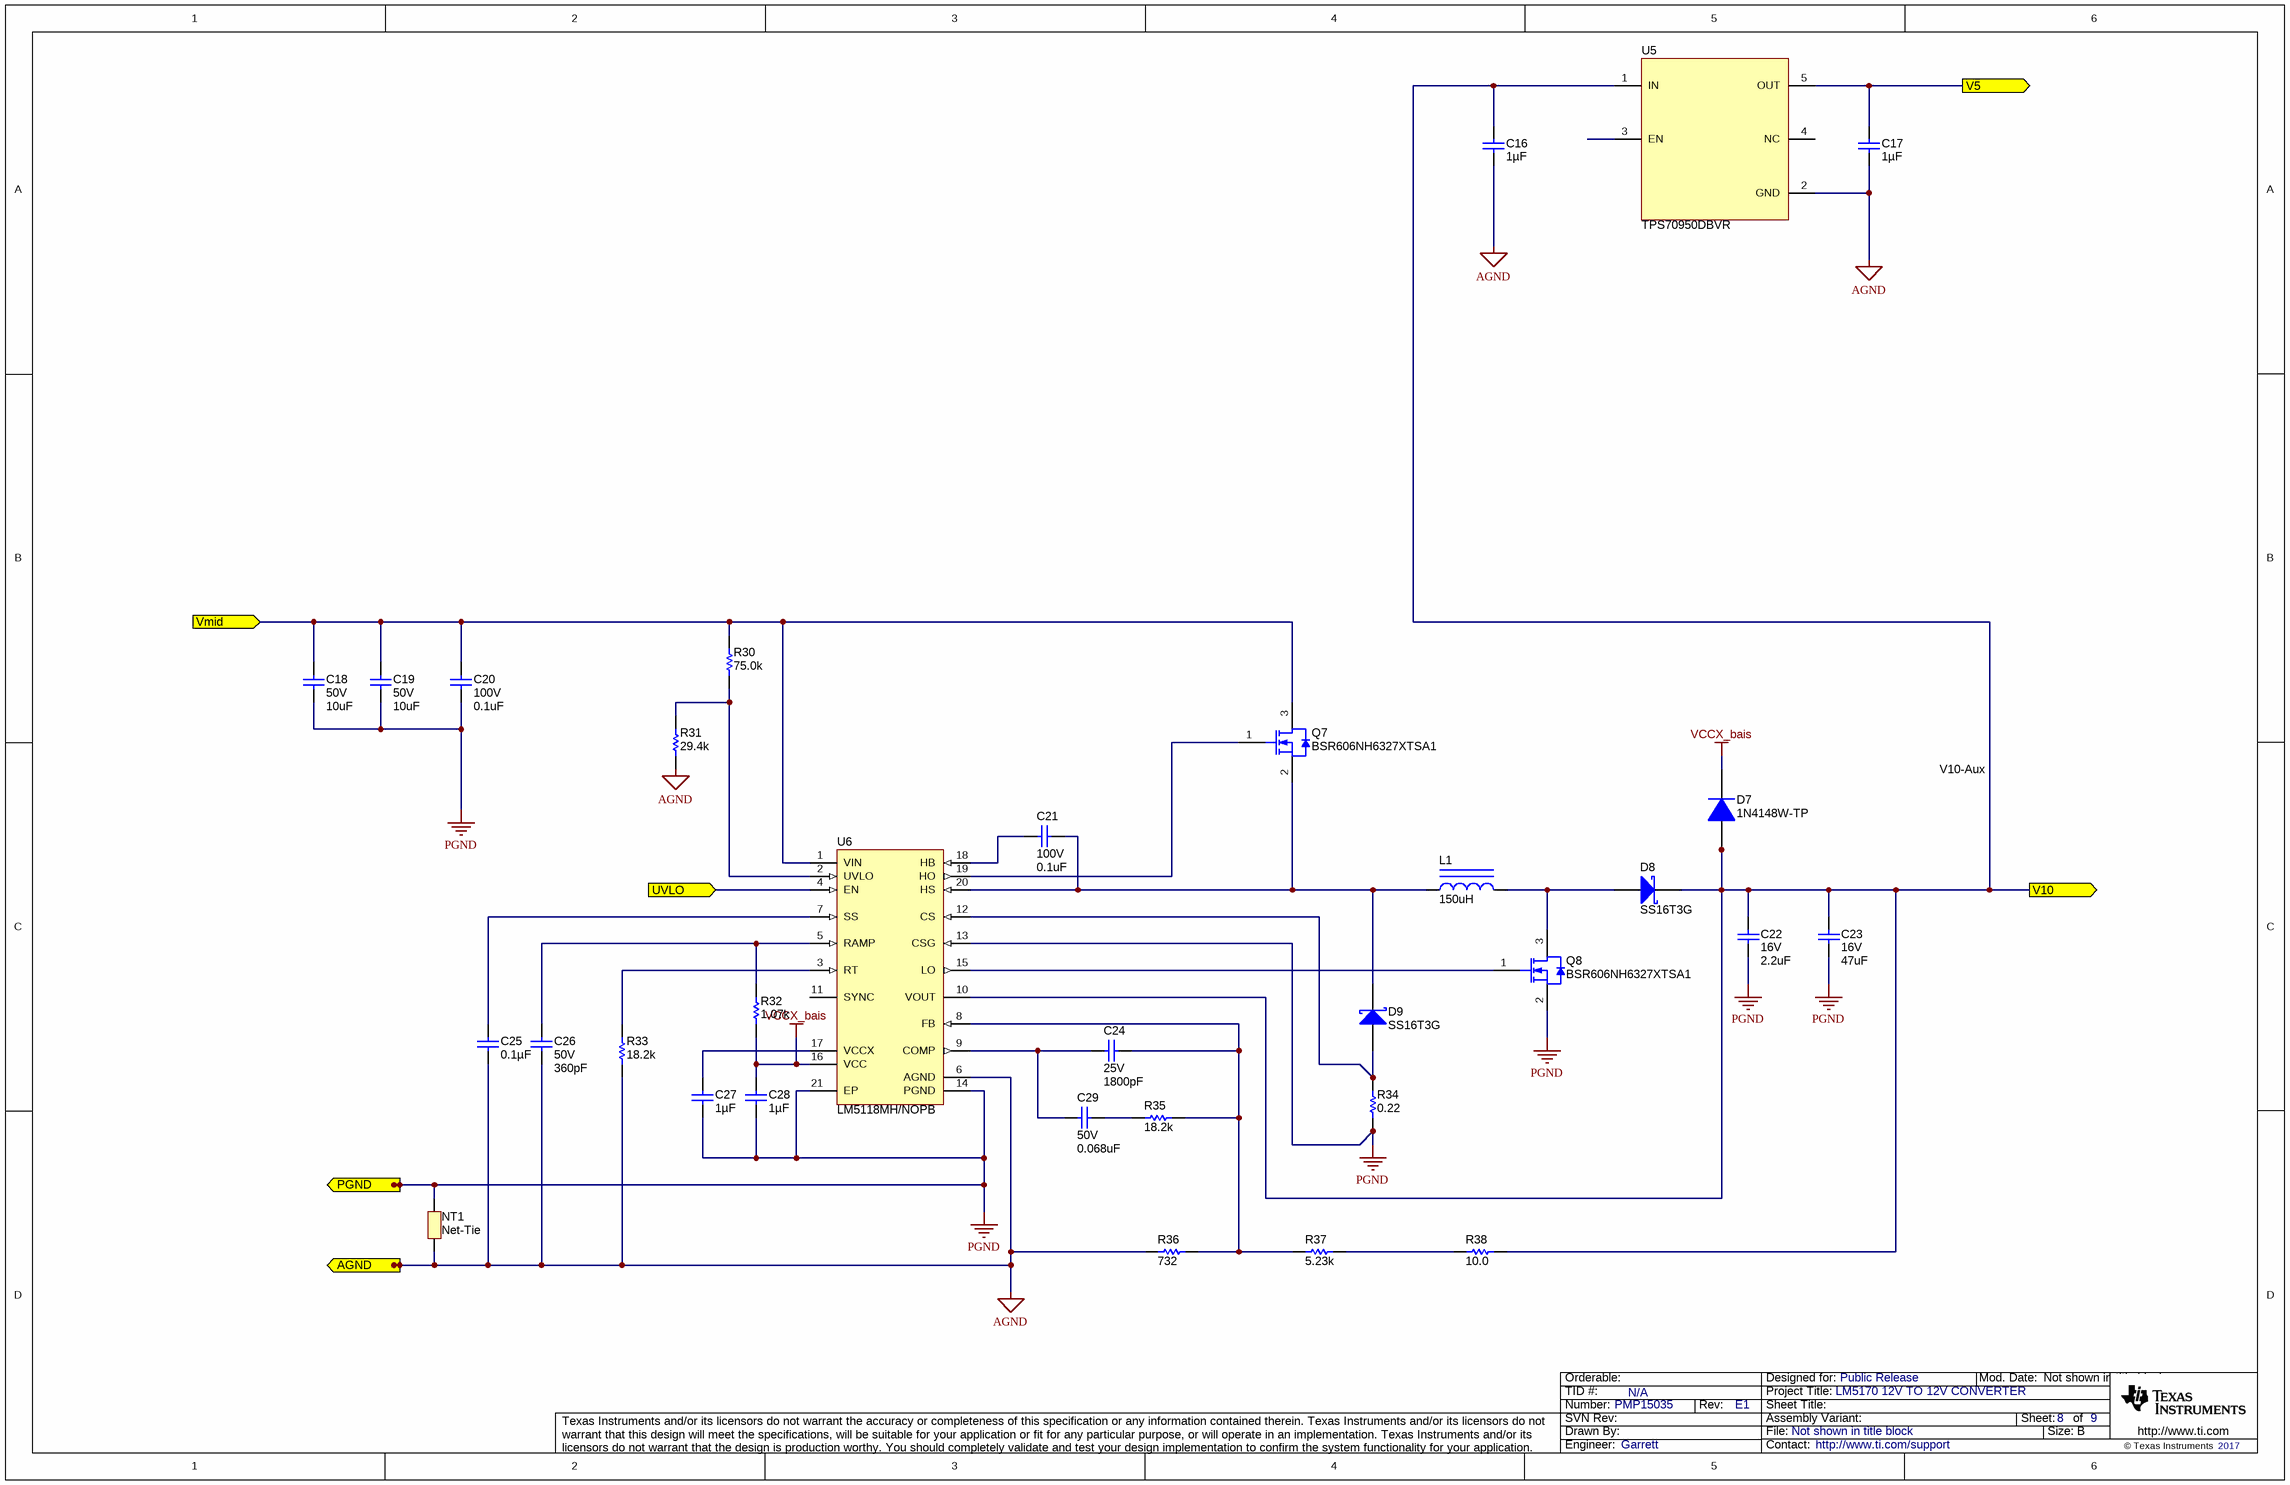
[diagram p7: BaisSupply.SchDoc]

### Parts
C16  ValueDisplayed: 1µF  [0805_HV]  (hidden comment: C2012X7S2A105K125AB)
C17  ValueDisplayed: 1µF  [0805_HV]  (hidden comment: C2012X7S2A105K125AB)
C18  VDC_V: 50V  ValueDisplayed: 10uF  [1206_180]  (hidden comment: GRT31CR61H106KE01L)
C19  VDC_V: 50V  ValueDisplayed: 10uF  [1206_180]  (hidden comment: GRT31CR61H106KE01L)
C20  VDC_V: 100V  ValueDisplayed: 0.1uF  [0805_HV]  (hidden comment: C2012X7R2A104K125AA)
C21  VDC_V: 100V  ValueDisplayed: 0.1uF  [0805_HV]  (hidden comment: C2012X7R2A104K125AA)
C22  VDC_V: 16V  ValueDisplayed: 2.2uF  [0805_HV]  (hidden comment: C2012X7R1C225K125AB)
C23  VDC_V: 16V  ValueDisplayed: 47uF  [1206]  (hidden comment: C3216X5R1C476M160AB)
C24  VDC_V: 25V  ValueDisplayed: 1800pF  [0603L]  (hidden comment: GCJ216R71E182KA01D)
C25  ValueDisplayed: 0.1µF  [0603L]  (hidden comment: GRM188R72A104KA35D)
C26  VDC_V: 50V  ValueDisplayed: 360pF  [0603L]  (hidden comment: GRM1885C1H361JA01D)
C27  ValueDisplayed: 1µF  [0603L]  (hidden comment: GRM188R71E105KA12D)
C28  ValueDisplayed: 1µF  [0603L]  (hidden comment: GRM188R71E105KA12D)
C29  VDC_V: 50V  ValueDisplayed: 0.068uF  [0603L]  (hidden comment: CGA3E2X7R1H683K080AA)
D7  1N4148W-TP  [SOD-123]
D8  SS16T3G  [SMA]
D9  SS16T3G  [SMA]
L1  ValueDisplayed: 150uH  [MSS1048]  (hidden comment: MSS1048-154KLB)
NT1  Net-Tie  [Net-Tie_10mil]  (net tie, no BOM)
Q7  BSR606NH6327XTSA1  [SOT-23]
Q8  BSR606NH6327XTSA1  [SOT-23]
R30  ValueDisplayed: 75.0k  [0603L]  (hidden comment: CRCW060375K0FKEA)
R31  ValueDisplayed: 29.4k  [0603L]  (hidden comment: CRCW060329K4FKEA)
R32  ValueDisplayed: 1.07k  [0603]  (hidden comment: RC0603FR-071K07L)
R33  ValueDisplayed: 18.2k  [0603L]  (hidden comment: CRCW060318K2FKEA)
R34  ValueDisplayed: 0.22  [1206]  (hidden comment: RL1632R-R220-F)
R35  ValueDisplayed: 18.2k  [0603]  (hidden comment: RC0603FR-0718K2L)
R36  ValueDisplayed: 732  [0603L]  (hidden comment: CRCW0603732RFKEA)
R37  ValueDisplayed: 5.23k  [0603L]  (hidden comment: CRCW06035K23FKEA)
R38  ValueDisplayed: 10.0  [0603L]  (hidden comment: CRCW060310R0FKEA)
U5  TPS70950DBVR  [DBV0005A_N]
U6  LM5118MH/NOPB  [MXA20A_N]

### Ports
AGND, PGND, UVLO, V5, V10, Vmid

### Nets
AGND: C16.2 C17.2 C25.2 C26.2 NT1.1 R31.1 R33.1 R36.1 U5.2(GND) U6.6(AGND) ; port AGND
PGND: C18.2 C19.2 C20.2 C22.2 C23.2 C27.2 C28.2 NT1.2 Q8.2(S) R34.1 U6.13(CSG) U6.14(PGND) U6.21(EP) ; port PGND
V5: C17.1 U5.5(OUT) ; port V5
VCC1: C16.1 C22.1 C23.1 D7.2(A) D8.1(K) R38.2 U5.1(IN) U6.10(VOUT) ; port V10
VCCX_bais: C28.1 D7.1(K) R32.1 U6.16(VCC)
Vmid: C18.1 C19.1 C20.1 Q7.3(D) R30.2 U6.1(VIN) ; port Vmid
UVLO: U6.4(EN) ; port UVLO
NetC21_1: C21.1 D9.1(K) L1.1 Q7.2(S) U6.20(HS)
NetC21_2: C21.2 U6.18(HB)
NetC24_1: C24.1 R35.2 R36.2 R37.1 U6.8(FB)
NetC24_2: C24.2 C29.2 U6.9(COMP)
NetC25_1: C25.1 U6.7(SS)
NetC26_1: C26.1 R32.2 U6.5(RAMP)
NetC27_1: C27.1 U6.17(VCCX)
NetC29_1: C29.1 R35.1
NetD8_2: D8.2(A) L1.2 Q8.3(D)
NetD9_2: D9.2(A) R34.2 U6.12(CS)
NetQ7_1: Q7.1(G) U6.19(HO)
NetQ8_1: Q8.1(G) U6.15(LO)
NetR30_1: R30.1 R31.2 U6.2(UVLO)
NetR33_2: R33.2 U6.3(RT)
NetR37_2: R37.2 R38.1

Not connected (* = marked no-connect by the designer): U5 3(EN) 4(NC); U6 11(SYNC)

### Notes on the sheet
- V10-Aux

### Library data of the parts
C16 C17 = C2012X7S2A105K125AB: as C37 on sheet LM5170ControllerStage1
C18 C19 = CMP-0009015-2: CAP, CERM, 10 uF, 50 V, +/- 10%, X5R, AEC-Q200 Grade 1, 1206; Manufacturer: MuRata; TaMin_C: -55°C; Polarized: N; SizeAreaWB_mm2: 10.92; Value1: Unknown; U/M: EA; Value: 10uF; TaMax_C: 85°C; SizeZ_mm: 1.8; SizeX_mm: 3.2; SizeY_mm: 1.6; Cap_Case: 1206; SizeArea_mm2: 5.12; CompType: Capacitor; AEC Qualified: Y; Cap_F: 10µF; AEC Grade: 1; AEC Category: Q200
C20 C21 = CMP-0007886-2: CAP, CERM, 0.1 uF, 100 V, +/- 10%, X7R, 0805; Manufacturer: TDK; TaMin_C: -55°C; ESR_ohm: 0.020726; Polarized: N; SizeAreaWB_mm2: 6.75; Value1: 0.020726 ohm; U/M: EA; Value: 0.1uF; TaMax_C: 125°C; SizeZ_mm: 1.45; SizeX_mm: 2; SizeY_mm: 1.25; Cap_Case: 0805; SizeArea_mm2: 2.5; CompType: Capacitor; Cap_F: 100nF; IRMS_A: 1.456A; AEC Category: Q200
C22 = CMP-0007867-2: as C45 on sheet LM5170ControllerStage1
C23 = CMP-0008653-2: CAP, CERM, 47 uF, 16 V, +/- 15%, X5R, 1206; Manufacturer: TDK; TaMin_C: -55°C; Polarized: N; SizeAreaWB_mm2: 10.92; Value1: Unknown; U/M: EA; Value: 47uF; TaMax_C: 85°C; SizeZ_mm: 1.35; SizeX_mm: 3.2; SizeY_mm: 1.6; SizeArea_mm2: 5.12; CompType: Capacitor; Cap_F: 47µF; AEC Category: Q200
C24 = CMP-0007124-4: CAP, CERM, 1800 pF, 25 V, +/- 10%, X7R, AEC-Q200 Grade 1, 0603; Manufacturer: MuRata; TaMin_C: -55°C; Polarized: N; SizeAreaWB_mm2: 4.68; Value1: Unknown; U/M: EA; Value: 1800pF; TaMax_C: 125°C; SizeZ_mm: 1; SizeX_mm: 1.6; SizeY_mm: 0.8; Cap_Case: 0603; SizeArea_mm2: 1.28; CompType: Capacitor; AEC Qualified: Y; Cap_F: 1.8nF; AEC Category: Q200
C25 = GRM188R72A104KA35D: as C42 on sheet LM5170ControllerStage1
C26 = CMP-0007212-4: CAP, CERM, 360 pF, 50 V, +/- 5%, C0G/NP0, 0603; Manufacturer: MuRata; TaMin_C: -55°C; Polarized: N; SizeAreaWB_mm2: 4.68; Value1: Unknown; U/M: EA; Value: 360pF; TaMax_C: 125°C; SizeZ_mm: 1; SizeX_mm: 1.6; SizeY_mm: 0.8; Cap_Case: 0603; SizeArea_mm2: 1.28; CompType: Capacitor; AEC Category: Q200
C27 C28 = GRM188R71E105KA12D: as C46 on sheet LM5170ControllerStage1
C29 = CMP-0007080-5: CAP, CERM, 0.068 uF, 50 V, +/- 10%, X7R, AEC-Q200 Grade 1, 0603; Manufacturer: TDK; TaMin_C: -55°C; ESR_ohm: 0.035979; Polarized: N; SizeAreaWB_mm2: 4.68; Value1: 0.035979 ohm; U/M: EA; TaMax_C: 125°C; SizeZ_mm: 1; SizeX_mm: 1.6; SizeY_mm: 0.8; Cap_Case: 0603; SizeArea_mm2: 1.28; CompType: Capacitor; AEC Qualified: Y; Cap_F: 68nF; IRMS_A: 8.86483dA; AEC Category: Q200
D7 = CMP-0076974-1: Diode, Switching, 100 V, 0.15 A, SOD-123; Manufacturer: Micro Commercial Components; SizeAreaWB_mm2: 13.095; Vr_V: 100V; SizeArea_mm2: 6.545; TJmax_C: 150°C; AEC Category: Q101; Value: 100V; SizeZ_mm: 1.35; Green_REACh: Incomplete; Io_A: 1.5dA; Vf_V: 1.25V; SizeY_mm: 1.7; Green_Lifecycle: Not Set; U/M: EA; Value1: 0.15A; SizeX_mm: 3.85
D8 D9 = CMP-0028585-1: Diode, Schottky, 60 V, 1 A, SMA; Manufacturer: ON Semiconductor; Io_A: 1A; Green_Lifecycle: Not Set; SizeAreaWB_mm2: 37.3428; Vr_V: 60V; Green_REACh: Incomplete; TJmax_C: 125°C; U/M: EA; Value: 60V; SizeZ_mm: 2.87; SizeX_mm: 5.59; SizeY_mm: 2.92; Vf_V: 7.2dV; Value2: 0.72V; SizeArea_mm2: 16.3228; AEC Category: Q101; RJC_CperW: 35
L1 = CMP-0061858-2: Inductor, Shielded Drum Core, Ferrite, 150 uH, 1.16 A, 0.37 ohm, SMD; Manufacturer: Coilcraft; Isat: 1.16A @ 30% inductance drop; Irms: 1.33A @ 40C rise; Green_Lifecycle: Not Set; SizeAreaWB_mm2: 146.4; DCR_ohm: 3.7d; Green_REACh: Incomplete; Value: 150uH; Imax_A: 1.16A; SizeZ_mm: 4.8; SizeX_mm: 10.2; SizeY_mm: 10; SizeArea_mm2: 102; Ind_H: 150µH; AEC Category: Q200
NT1 = Net-Tie: as NT2 on sheet LM5170ControllerStage1
Q7 Q8 = CMP-0079125-1: MOSFET, N-CH, 60 V, 2.3 A, AEC-Q101, SOT-23; Manufacturer: Infineon Technologies; Alternate Manufacturer: None; ChType: N; QgTyp_nC: 3.7; SizeAreaWB_mm2: 14; SizeArea_mm2: 7.5; IdsMax_A: 2.3A; AEC Qualified: Y; VdsMax_V: 60V; Rdson45_ohm: 0.09; Vgs_V: 20V; AEC Category: Q101; Value: 60V; SizeZ_mm: 1.1; SizeY_mm: 3; Value2: 3.7 nC; U/M: EA; Value1: 0.09 ohm; SizeX_mm: 2.5
R30 = CRCW060375K0FKEA: RES, 75.0 k, 1%, 0.1 W, 0603; Manufacturer: Vishay-Dale; CompType: Resistor; Value: 75.0k; Res_ohm: 75000; Value_Code: 75k0; Tolerance_%: 1; Power_W: 0.1; Value2: 0.1W; VDC_V: 75; TempCo: 100 ppm/C; EIA_Code: E96; U/M: EA
R31 = CRCW060329K4FKEA: RES, 29.4 k, 1%, 0.1 W, 0603; Manufacturer: Vishay-Dale; CompType: Resistor; Value: 29.4k; Res_ohm: 29400; Value_Code: 29k4; Tolerance_%: 1; Power_W: 0.1; Value2: 0.1W; VDC_V: 75; TempCo: 100 ppm/C; EIA_Code: E96; U/M: EA
R32 = CMP-0022866-3: RES, 1.07 k, 1%, 0.1 W, 0603; Manufacturer: Yageo America; Power_W: 100mW; TempCo: 200 ppm/C; Value_Code: 1k07; U/M: EA; Value: 1.07k; EIA_Code: E96; SizeX_mm: 1.6; SizeY_mm: 0.8; SizeZ_mm: 1; Value2: 0.1W; SizeArea_mm2: 1.28; CompType: Resistor; VDC_V: 150V; AEC Category: Q200
R33 = CRCW060318K2FKEA: RES, 18.2 k, 1%, 0.1 W, 0603; Manufacturer: Vishay-Dale; CompType: Resistor; Value: 18.2k; Res_ohm: 18200; Value_Code: 18k2; Tolerance_%: 1; Power_W: 0.1; Value2: 0.1W; VDC_V: 75; TempCo: 100 ppm/C; EIA_Code: E96; U/M: EA
R34 = CMP-0079171-1: RES, 0.22, 1%, 0.5 W, 1206; Manufacturer: Susumu Co Ltd; Value_Code: R220; SizeAreaWB_mm2: 10.92; SizeArea_mm2: 5.12; AEC Qualified: N; AEC Category: Q200; Res_ohm: 2.2d; Value: 0.22; SizeZ_mm: 1.35; EIA_Code: E96; TempCo: 100 ppm/C; Power_W: 500mW; SizeY_mm: 1.6; Value2: 0.5W; CompType: Resistor; SizeX_mm: 3.2
R35 = CMP-0022850-3: RES, 18.2 k, 1%, 0.1 W, 0603; Manufacturer: Yageo America; Power_W: 100mW; TempCo: 200 ppm/C; Value_Code: 18k2; U/M: EA; Value: 18.2k; EIA_Code: E96; SizeX_mm: 1.6; SizeY_mm: 0.8; SizeZ_mm: 1; Value2: 0.1W; SizeArea_mm2: 1.28; CompType: Resistor; VDC_V: 150V; AEC Category: Q200
R36 = CRCW0603732RFKEA: RES, 732, 1%, 0.1 W, 0603; Manufacturer: Vishay-Dale; CompType: Resistor; Value: 732; Value_Code: 732R; Tolerance_%: 1; Power_W: 0.1; Value2: 0.1W; VDC_V: 75; TempCo: 100 ppm/C; EIA_Code: E96; U/M: EA
R37 = CRCW06035K23FKEA: RES, 5.23 k, 1%, 0.1 W, 0603; Manufacturer: Vishay-Dale; CompType: Resistor; Value: 5.23k; Res_ohm: 5230; Value_Code: 5k23; Tolerance_%: 1; Power_W: 0.1; Value2: 0.1W; VDC_V: 75; TempCo: 100 ppm/C; EIA_Code: E96; U/M: EA
R38 = CRCW060310R0FKEA: RES, 10.0, 1%, 0.1 W, 0603; Manufacturer: Vishay-Dale; CompType: Resistor; Value: 10.0; Res_ohm: 10; Value_Code: 10R0; Tolerance_%: 1; Power_W: 0.1; Value2: 0.1W; VDC_V: 75; TempCo: 100 ppm/C; EIA_Code: E96; U/M: EA
U5 = TPS70950DBVR: 150-mA, 30-V, 1-uA IQ Voltage Regulators with Enable, DBV0005A; Alternate PartNumber: TPS70950DBVT; Manufacturer: Texas Instruments; SymbolCreator: Altium; CompType: IC; U/M: EA
U6 = LM5118MH/NOPB: Wide Voltage Range Buck-Boost Controller, 20-pin TSSOP-EP, Pb-Free; Manufacturer: Texas Instruments; PackageTopMarking: NSUZXYTT*LM5118*MH; PowerWise: Y; CompType: Switcher

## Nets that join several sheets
AGND: AnalogControl2 (9 pins), AnalogControl1 (15 pins), LM5170ControllerStage1 (61 pins), LM5170ControllerStage2 (42 pins), BaisSupply (10 pins)
DIR1: AnalogControl2 (U2.12), AnalogControl1 (Q4.1 U2.4), LM5170ControllerStage1 (J1.8 Q9.1 U9.44)
EN1: AnalogControl2 (U2.10 U2.13), AnalogControl1 (U2.2 U2.5), LM5170ControllerStage1 (J1.2 U9.39), LM5170ControllerStage2 (U16.39)
EN2: LM5170ControllerStage1 (J1.5 U9.43), LM5170ControllerStage2 (U16.43)
nFAULT: LM5170ControllerStage1 (D14.2 U9.27), LM5170ControllerStage2 (U16.27)
PGND: LM5170PowerStage2 (30 pins), LM5170PowerStage1 (42 pins), LM5170ControllerStage1 (C45.2 NT2.2 U9.18), LM5170ControllerStage2 (C75.2 NT3.2 U16.18), BaisSupply (13 pins)
REF: AnalogControl2 (R23.2 R24.1), AnalogControl1 (5 pins)
V5: AnalogControl2 (C9.1 U4.8), AnalogControl1 (7 pins), LM5170ControllerStage1 (13 pins), LM5170ControllerStage2 (6 pins), BaisSupply (C17.1 U5.5)
V12_A: LM5170PowerStage1 (14 pins), AnalogControl1 (R2.2)
V12_B: AnalogControl2 (R16.1), LM5170PowerStage2 (14 pins)
VCC1: LM5170ControllerStage1 (5 pins), LM5170ControllerStage2 (5 pins), BaisSupply (8 pins)
Vmid: AnalogControl2 (R17.2), LM5170PowerStage2 (22 pins), LM5170PowerStage1 (34 pins), AnalogControl1 (R1.1), LM5170ControllerStage1 (C38.1 R63.1 U9.6), LM5170ControllerStage2 (C69.1 U16.6), BaisSupply (6 pins)
CS1A1: LM5170PowerStage1 (R103.1), LM5170ControllerStage1 (C51.2 C53.1 U9.1)
CS1A2: LM5170PowerStage2 (R116.1), LM5170ControllerStage2 (C70.1 C71.1 U16.36)
CS1B1: LM5170PowerStage1 (R102.1), LM5170ControllerStage1 (C51.1 C52.1 U9.2)
CS1B2: LM5170PowerStage2 (R117.1), LM5170ControllerStage2 (C70.2 C72.1 U16.35)
CS2A1: LM5170PowerStage1 (R93.1), LM5170ControllerStage1 (C39.1 C40.1 U9.36)
CS2A2: LM5170PowerStage2 (R126.1), LM5170ControllerStage2 (C82.2 C84.1 U16.1)
CS2B1: LM5170PowerStage1 (R92.1), LM5170ControllerStage1 (C39.2 C41.1 U9.35)
CS2B2: LM5170PowerStage2 (R127.1), LM5170ControllerStage2 (C82.1 C83.1 U16.2)
DIR2: AnalogControl2 (U2.9), AnalogControl1 (Q3.1 U2.1), LM5170ControllerStage1 (Q9.3 R51.1), LM5170ControllerStage2 (U16.44)
HO11: LM5170PowerStage1 (R94.1 R98.1), LM5170ControllerStage1 (U9.15)
HO12: LM5170PowerStage2 (R118.1 R122.1), LM5170ControllerStage2 (U16.22)
HO21: LM5170PowerStage1 (R106.1 R110.1), LM5170ControllerStage1 (U9.22)
HO22: LM5170PowerStage2 (R130.1 R134.1), LM5170ControllerStage2 (U16.15)
ISETA1: AnalogControl1 (R7.2 R10.1), LM5170ControllerStage1 (C49.1 U9.45)
ISETA2: AnalogControl2 (R22.2 R25.1), LM5170ControllerStage2 (C79.1 U16.45)
LO11: LM5170PowerStage1 (R95.1 R96.1), LM5170ControllerStage1 (U9.17)
LO12: LM5170PowerStage2 (R119.1 R120.1), LM5170ControllerStage2 (U16.20)
LO21: LM5170PowerStage1 (R107.1 R108.1), LM5170ControllerStage1 (U9.20)
LO22: LM5170PowerStage2 (R131.1 R132.1), LM5170ControllerStage2 (U16.17)
OTP: LM5170ControllerStage1 (7 pins), LM5170ControllerStage2 (U17.3 U18.3)
SW11: LM5170PowerStage1 (22 pins), LM5170ControllerStage1 (C48.2 U9.13)
SW12: LM5170PowerStage2 (22 pins), LM5170ControllerStage2 (C73.1 U16.24)
SW21: LM5170PowerStage1 (22 pins), LM5170ControllerStage1 (C43.1 U9.24)
SW22: LM5170PowerStage2 (22 pins), LM5170ControllerStage2 (C78.2 U16.13)
SYNC: LM5170ControllerStage1 (R54.2 U9.41), LM5170ControllerStage2 (U16.40)
UVLO: LM5170ControllerStage1 (C37.1 D15.1 J1.20 U9.10), LM5170ControllerStage2 (C68.1 U16.10), BaisSupply (U6.4)

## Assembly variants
001: not fitted FID1 FID2 FID3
